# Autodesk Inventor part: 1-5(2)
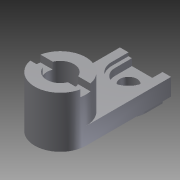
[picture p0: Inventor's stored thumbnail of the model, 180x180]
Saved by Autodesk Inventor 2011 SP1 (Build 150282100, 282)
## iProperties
Created: 2014-02
Part Number: 1-5(2)
Document SubType Name: Modeling
Designer: Administrator
Density: 1 g/cm^3
Author: Administrator
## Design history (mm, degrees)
sketch "草图1"
  geometry: C1 r 7.5 at (0, 0); 1 further point
  constraints: 1 centre point, 1 coincident
  dimensions: "d0" = 15 diameter of C1
extrude "拉伸1" new body sketch "草图1" distance "d1" = 15; taper "d2" = 0 deg
sketch "草图2"
  geometry: L1 (-7.5, 0)-(7.5, 0); L2 (7.5, 0)-(7.5, 25); L3 (7.5, 25)-(-7.5, 25); L4 (-7.5, 25)-(-7.5, 0); 1 further point
  constraints: 8 end point, 2 parallel, 1 horizontal, 1 horizontal alignment, 1 perpendicular, 1 other
  dimensions: "d3" = 25 distance of L1.end L2.end
extrude "拉伸2" join sketch "草图2" distance "d4" = 5; taper "d5" = 0 deg
sketch "草图3"
  geometry: L1 (7.5, 25)-(-7.5, 25) reference; L2 (-5, 20)-(-5, 25); L3 (5, 20)-(5, 25); A1 r 5 centre (0, 20) between (-5, 20) and (5, 20); 1 further point
  constraints: 4 end point, 2 perpendicular, 2 point on circle, 2 point on line, 2 tangent, 1 centre point, 1 midpoint
extrude "拉伸3" join sketch "草图3" distance "d7" = 3; taper "d8" = 0 deg
sketch "草图4"
  geometry: C1 r 2.5 at (0, 20); A1 r 5 centre (0, 20) between (-5, 20) and (5, 20) reference; 1 further point
  constraints: 1 centre point, 1 coincident
  dimensions: "d9" = 5 diameter of C1
extrude "拉伸4" cut sketch "草图4" distance "d10" = 10; taper "d11" = 0 deg
sketch "草图5"
  geometry: C1 r 7.5 at (0, 0) reference; C2 r 4 at (0, 0)
  constraints: 1 centre point, 1 coincident
  dimensions: "d12" = 8 diameter of C2
extrude "拉伸5" cut sketch "草图5" stored distance "d13" = 10; taper "d14" = 0 deg
sketch "草图6"
  geometry: L1 (-7.5, 25)-(7.5, 25) reference; L2 (-5, 20)-(-5, 25); L3 (5, 20)-(5, 25); C1 r 2.5 at (0, 20) reference; A1 r 5 centre (0, 20) between (-5, 20) and (5, 20) reference; A2 r 5 centre (0, 20) between (-5, 20) and (5, 20)
  constraints: 4 end point, 4 tangent, 3 point on line, 2 perpendicular, 2 point on circle, 1 centre point, 1 coincident
extrude "拉伸6" cut sketch "草图6" distance "d15" = 1; taper "d16" = 0 deg
sketch "草图7"
  geometry: L1 (-5, 25)-(5, 25) reference; L2 (-4, 20)-(-4, 25); L3 (4, 20)-(4, 25); C1 r 2.5 at (0, 20) reference; A1 r 5 centre (0, 20) between (-5, 20) and (5, 20) reference; A2 r 4 centre (0, 20) between (-4, 20) and (4, 20); 1 further point
  constraints: 4 end point, 2 perpendicular, 2 point on circle, 2 point on line, 2 tangent, 1 centre point, 1 coincident
  dimensions: "d17" = 8 diameter of A2
extrude "拉伸7" cut sketch "草图7" distance "d18" = 2; taper "d19" = 0 deg
sketch "草图8"
  geometry: L1 (-8.089, -1.5)-(8.021, -1.5); L2 (8.021, -1.5)-(8.021, 1.5); L3 (8.021, 1.5)-(-8.089, 1.5); L4 (-8.089, 1.5)-(-8.089, -1.5); C1 r 4 at (0, 0) reference; 1 further point
  constraints: 8 end point, 2 parallel, 1 horizontal, 1 horizontal alignment, 1 midpoint, 1 perpendicular
  dimensions: "d21" = 3 distance of L1.end L2.end
extrude "拉伸8" cut sketch "草图8" distance "d22" = 2; taper "d23" = 0 deg
node "实体1"
